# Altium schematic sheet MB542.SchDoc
size A4; Revision: B.2(PCB.SCH)
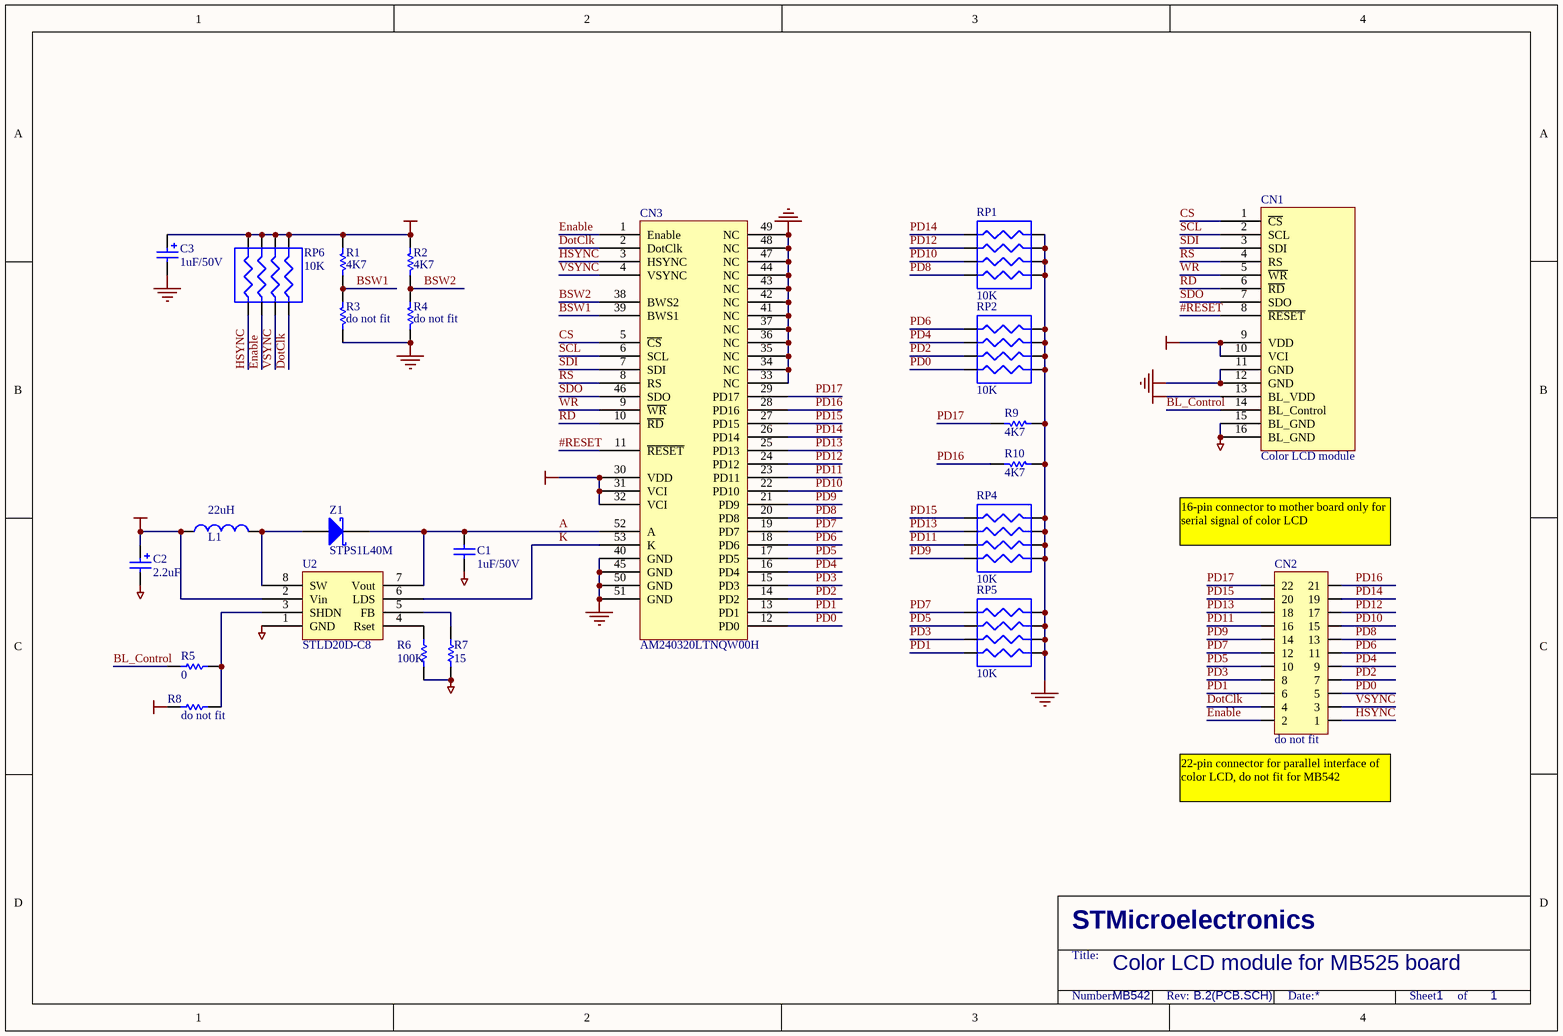
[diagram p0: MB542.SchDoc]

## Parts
C1  1uF/50V  [0603]
C2  2.2uF  [TAN-A]
C3  1uF/50V  [TAN-B]
CN1  Color LCD module  [AM240320A]
CN2  do not fit  [2*11P]
CN3  AM240320LTNQW00H
L1  22uH  [3225]
R1  4K7  [0603]
R2  4K7  [0603]
R3  do not fit  [0603]
R4  do not fit  [0603]
R5  0  [0603]
R6  100K  [0603]
R7  15  [0603]
R8  do not fit  [0603]
R9  4K7  [0603]
R10  4K7  [0603]
RP1  10K  [RES-4B]
RP2  10K  [RES-4B]
RP4  10K  [RES-4B]
RP5  10K  [RES-4B]
RP6  10K  [RES-4B]
U2  STLD20D-C8  [SOT23-8L]
Z1  STPS1L40M  [1R1C]

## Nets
BLGND: C1.1 C2.2 CN1.15(BL_GND) CN1.16(BL_GND) R6.1 R7.1 U2.1(GND)
BLVDD: C2.1 CN1.13(BL_VDD) L1.1 R8.2 U2.2(Vin)
GND: C3.2 CN1.11(GND) CN1.12(GND) CN3.33(NC) CN3.34(NC) CN3.35(NC) CN3.36(NC) CN3.37(NC) CN3.40(GND) CN3.41(NC) CN3.42(NC) CN3.43(NC) CN3.44(NC) CN3.45(GND) CN3.47(NC) CN3.48(NC) CN3.49(NC) CN3.50(GND) CN3.51(GND) R3.1 R4.1 R9.1 R10.1 RP1.2(R1) RP1.4(R3) RP1.6(R2) RP1.8(R0) RP2.2(R1) RP2.4(R3) RP2.6(R2) RP2.8(R0) RP4.2(R1) RP4.4(R3) RP4.6(R2) RP4.8(R0) RP5.2(R1) RP5.4(R3) RP5.6(R2) RP5.8(R0)
VDD: C3.1 CN1.9(VDD) CN1.10(VCI) CN3.30(VDD) CN3.31(VCI) CN3.32(VCI) R1.2 R2.2 RP6.2(R1) RP6.4(R3) RP6.6(R2) RP6.8(R0)
#RESET: CN1.8(~{RESET}) CN3.11(~{RESET})
A: C1.2 CN3.52(A) U2.7(Vout) Z1.2(K)
BL_Control: CN1.14(BL_Control) R5.2
BSW1: CN3.39(BWS1) R1.1 R3.2
BSW2: CN3.38(BWS2) R2.1 R4.2
CS: CN1.1(~{CS}) CN3.5(~{CS})
DotClk: CN2.4 CN3.2(DotClk) RP6.7(R1)
Enable: CN2.2 CN3.1(Enable) RP6.3(R2)
HSYNC: CN2.1 CN3.3(HSYNC) RP6.1(R0)
K: CN3.53(K) U2.6(LDS)
PD0: CN2.5 CN3.12(PD0) RP2.7(R1)
PD1: CN2.6 CN3.13(PD1) RP5.7(R1)
PD2: CN2.7 CN3.14(PD2) RP2.5(R3)
PD3: CN2.8 CN3.15(PD3) RP5.5(R3)
PD4: CN2.9 CN3.16(PD4) RP2.3(R2)
PD5: CN2.10 CN3.17(PD5) RP5.3(R2)
PD6: CN2.11 CN3.18(PD6) RP2.1(R0)
PD7: CN2.12 CN3.19(PD7) RP5.1(R0)
PD8: CN2.13 CN3.20(PD8) RP1.7(R1)
PD9: CN2.14 CN3.21(PD9) RP4.7(R1)
PD10: CN2.15 CN3.22(PD10) RP1.5(R3)
PD11: CN2.16 CN3.23(PD11) RP4.5(R3)
PD12: CN2.17 CN3.24(PD12) RP1.3(R2)
PD13: CN2.18 CN3.25(PD13) RP4.3(R2)
PD14: CN2.19 CN3.26(PD14) RP1.1(R0)
PD15: CN2.20 CN3.27(PD15) RP4.1(R0)
PD16: CN2.21 CN3.28(PD16) R10.2
PD17: CN2.22 CN3.29(PD17) R9.2
RD: CN1.6(~{RD}) CN3.10(~{RD})
RS: CN1.4(RS) CN3.8(RS)
SCL: CN1.2(SCL) CN3.6(SCL)
SDI: CN1.3(SDI) CN3.7(SDI)
SDO: CN1.7(SDO) CN3.46(SDO)
VSYNC: CN2.3 CN3.4(VSYNC) RP6.5(R3)
WR: CN1.5(~{WR}) CN3.9(~{WR})
NetL1_2: L1.2 U2.8(SW) Z1.1(A)
NetR5_1: R5.1 R8.1 U2.3(SHDN)
NetR6_2: R6.2 U2.4(Rset)
NetR7_2: R7.2 U2.5(FB)

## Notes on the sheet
- 16-pin connector to mother board only for serial signal of color LCD
- (near CN2) 22-pin connector for parallel interface of color LCD, do not fit for MB542
- Color LCD module for MB525 board
- MB542
- 1

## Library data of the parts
C1 = CAP: Capacitor; Value: 100pF
C2 C3 = Cap Pol1: Polarized Capacitor (Radial); Value: 100pF
CN1 = ColorLCD_module
CN2 = IDC22: Part Field 1: 17-Jul-2002: Re-released for DXP Platform.
L1 = Inductor: Value: 100uH
R1-R10 = Res1: Resistor; Value: 1K
RP1 RP2 RP4-RP6 = RES4B
Z1 = D Schottky: Schottky Diode; Code - JEDEC: DO-214-AA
